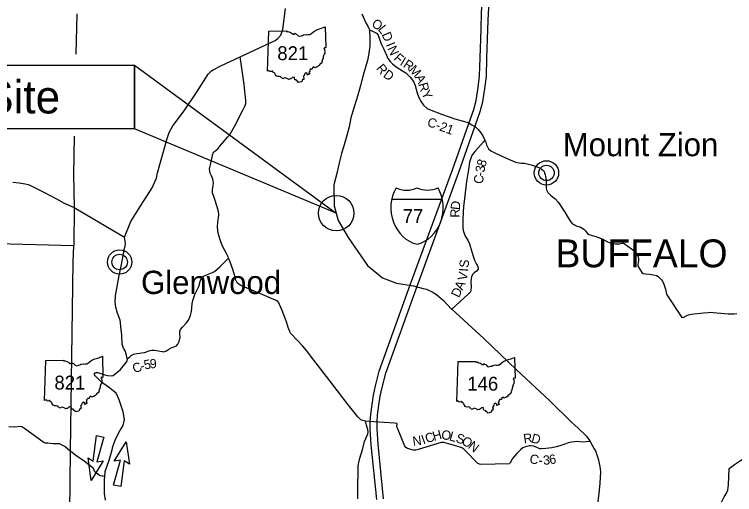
# Model space of a CAD drawing. Extents: x -452339 to 6403467, y -1 to 1814750.
# Drawn here: x -67891 to -44654, y 1625369 to 1640875 of the extents above; entities that cross this region are included whole.
import ezdxf

# ---------------------------------------------------------------- set-up
doc = ezdxf.new("R2010")
doc.units = 0
for name, color, linetype in [('Default', 7, 'Continuous'), ('GM_X_Adjacent_County_Text', 7, 'Continuous'), ('GM_X_County', 7, 'Continuous'), ('GM_X_County_Road', 7, 'Continuous'), ('GM_X_County_Road_Text', 7, 'Continuous'), ('GM_X_Minor_Lake_Text', 7, 'Continuous'), ('GM_X_Section', 7, 'Continuous'), ('GM_X_Section_Text', 7, 'Continuous'), ('GM_X_Township_ROW', 7, 'Continuous')]:
    doc.layers.add(name, color=color, linetype=linetype)

msp = doc.modelspace()

# ---------------------------------------------------------------- linework, layer by layer
at = {"layer": 'Default'}
for p, q in [((-59723, 1639044), (-59681, 1640335)), ((-66916, 1628409), (-66874, 1629700)), ((-53620, 1628373), (-53578, 1629664)), ((-65346, 1626449), (-65238, 1627275)), ((-65238, 1627275), (-65005, 1627228)), ((-65005, 1627228), (-65229, 1626424)), ((-64669, 1626448), (-64288, 1627077)), ((-64288, 1627077), (-64182, 1626349)), ((-65410, 1625829), (-65516, 1626557)), ((-65516, 1626557), (-65346, 1626449)), ((-65030, 1626458), (-65410, 1625829)), ((-65229, 1626424), (-65030, 1626458)), ((-64692, 1625678), (-64469, 1626482)), ((-64469, 1626482), (-64669, 1626448)), ((-64352, 1626458), (-64460, 1625631)), ((-64182, 1626349), (-64352, 1626458)), ((-64460, 1625631), (-64692, 1625678))]:
    msp.add_line(p, q, dxfattribs=at)
for points in [[(-64339, 1633684), (-64133, 1634190), (-63810, 1634709), (-63450, 1635280), (-63304, 1635583), (-63277, 1635756), (-63038, 1636604), (-62979, 1636807), (-62903, 1637066), (-62775, 1637282), (-62415, 1637762), (-62012, 1638356), (-61637, 1638943), (-61528, 1639048), (-61478, 1639088), (-61229, 1639211), (-60612, 1639503), (-59478, 1640037), (-59391, 1640096), (-59300, 1640208), (-59232, 1640383), (-59143, 1641070)], [(-59681, 1640335), (-59109, 1640343), (-59118, 1640328), (-59064, 1640324), (-59007, 1640297), (-58958, 1640280), (-58899, 1640239), (-58863, 1640239), (-58848, 1640273), (-58821, 1640247), (-58789, 1640242), (-58733, 1640180), (-58687, 1640167), (-58631, 1640188), (-58591, 1640191), (-58560, 1640212), (-58482, 1640230), (-58460, 1640219), (-58418, 1640222), (-58397, 1640230), (-58361, 1640223), (-58297, 1640270), (-58232, 1640325), (-58130, 1640377), (-57980, 1640426), (-57860, 1640471), (-57843, 1639801)], [(-56435, 1640374), (-56385, 1640358), (-56246, 1640292), (-56207, 1640264), (-56159, 1640209), (-56099, 1640045), (-56045, 1639904), (-55974, 1639757), (-55890, 1639554), (-55838, 1639454), (-55771, 1639359), (-55692, 1639276), (-55575, 1639185), (-55369, 1639057), (-55261, 1638988), (-55196, 1638929), (-55117, 1638846), (-55044, 1638753), (-55007, 1638683), (-54964, 1638574), (-54899, 1638347), (-54854, 1638219), (-54789, 1638084), (-54689, 1637947), (-54568, 1637840), (-54447, 1637781), (-54113, 1637659), (-53682, 1637499), (-53371, 1637418), (-53291, 1637391), (-53220, 1637358), (-53127, 1637311), (-53011, 1637242), (-52928, 1637161), (-52840, 1637056), (-52777, 1636954), (-52708, 1636813)], [(-57843, 1639801), (-57860, 1639791), (-57888, 1639796), (-57906, 1639777), (-57883, 1639746), (-57873, 1639713), (-57882, 1639676), (-57873, 1639646), (-57879, 1639621), (-57896, 1639595), (-57902, 1639572), (-57917, 1639546), (-57916, 1639532), (-57930, 1639522), (-57927, 1639479), (-57934, 1639456), (-57932, 1639436), (-57955, 1639431), (-57949, 1639414), (-57964, 1639401), (-57961, 1639380), (-57977, 1639365), (-57961, 1639337), (-57974, 1639328), (-57984, 1639294), (-58014, 1639287), (-58071, 1639225), (-58092, 1639201), (-58115, 1639195), (-58128, 1639171), (-58156, 1639171), (-58200, 1639154), (-58227, 1639183), (-58276, 1639148), (-58282, 1639108), (-58343, 1639109), (-58341, 1639089), (-58354, 1639083), (-58367, 1639063), (-58360, 1639026), (-58389, 1639017), (-58385, 1638996), (-58366, 1638983), (-58358, 1638943), (-58389, 1638951), (-58414, 1638917), (-58440, 1638925), (-58432, 1638954), (-58475, 1638989), (-58516, 1638961), (-58538, 1638917), (-58538, 1638887), (-58569, 1638869), (-58549, 1638827), (-58553, 1638798), (-58552, 1638770), (-58591, 1638772), (-58614, 1638697)], [(-60980, 1633002), (-60992, 1633046), (-61051, 1633151), (-61175, 1633395), (-61256, 1633592), (-61312, 1633814), (-61330, 1633906), (-61339, 1634006), (-61324, 1634177), (-61296, 1634393), (-61294, 1634437), (-61321, 1634551), (-61417, 1634861), (-61435, 1634931), (-61468, 1635024), (-61496, 1635100), (-61499, 1635156), (-61497, 1635214), (-61480, 1635355), (-61471, 1635441), (-61475, 1635497), (-61488, 1635555), (-61528, 1635667), (-61571, 1635745), (-61583, 1635806), (-61594, 1635886), (-61563, 1636018), (-61487, 1636371), (-61479, 1636393), (-61457, 1636427), (-61421, 1636461), (-61376, 1636492), (-61326, 1636530), (-61259, 1636615), (-61015, 1636907), (-60956, 1636979), (-60794, 1637252), (-60527, 1637759), (-60442, 1637935), (-60423, 1638001), (-60422, 1638093), (-60477, 1638614), (-60559, 1639209), (-60612, 1639503)], [(-58614, 1638697), (-58681, 1638683), (-58727, 1638675), (-58743, 1638708), (-58776, 1638726), (-58798, 1638760), (-58846, 1638764), (-58857, 1638811), (-58862, 1638849), (-58927, 1638840), (-58945, 1638817), (-58968, 1638810), (-58982, 1638787), (-59013, 1638785), (-59047, 1638774), (-59069, 1638797), (-59125, 1638820), (-59150, 1638832), (-59202, 1638813), (-59213, 1638792), (-59254, 1638801), (-59264, 1638825), (-59289, 1638833), (-59294, 1638858), (-59348, 1638872), (-59389, 1638867), (-59461, 1638887), (-59466, 1638921), (-59490, 1638963), (-59503, 1638991), (-59548, 1639013), (-59558, 1639047), (-59572, 1639046), (-59586, 1639032), (-59637, 1639026), (-59657, 1639040), (-59685, 1639064), (-59723, 1639044)], [(-52708, 1636813), (-52757, 1636763), (-52999, 1636481), (-53019, 1636458)], [(-52708, 1636813), (-52685, 1636749), (-52656, 1636660), (-52629, 1636596), (-52590, 1636530), (-52520, 1636471), (-52391, 1636403), (-52226, 1636326), (-52063, 1636256), (-51823, 1636144), (-51728, 1636103), (-51670, 1636088), (-51544, 1636075), (-51438, 1636068), (-51349, 1636053), (-51215, 1636014), (-51060, 1635968), (-50969, 1635929), (-50915, 1635905), (-50879, 1635881), (-50843, 1635843), (-50802, 1635799), (-50786, 1635747), (-50771, 1635700)], [(-53019, 1636458), (-53020, 1636458), (-53078, 1636390), (-53131, 1636315), (-53169, 1636237), (-53207, 1636105), (-53235, 1635863), (-53299, 1635483), (-53366, 1634931), (-53399, 1634660), (-53414, 1634495), (-53418, 1634227), (-53424, 1633992), (-53410, 1633895), (-53347, 1633717), (-53263, 1633585), (-53209, 1633470), (-53185, 1633396), (-53151, 1633286), (-53088, 1633067), (-53050, 1632944), (-52983, 1632813), (-52948, 1632759), (-52930, 1632697), (-52930, 1632647), (-52983, 1632586), (-53056, 1632535), (-53098, 1632490), (-53146, 1632411), (-53166, 1632255), (-53154, 1632067), (-53159, 1631982), (-53172, 1631914), (-53246, 1631841), (-53777, 1631355)], [(-50771, 1635700), (-50759, 1635647), (-50738, 1635511), (-50729, 1635433), (-50733, 1635331), (-50734, 1635280), (-50719, 1635209), (-50680, 1635123), (-50596, 1635035), (-50541, 1634992), (-50493, 1634962), (-50442, 1634919), (-50344, 1634815), (-50289, 1634736), (-50219, 1634623), (-50135, 1634492), (-50021, 1634304), (-49952, 1634191), (-49905, 1634138), (-49846, 1634087), (-49747, 1634041), (-49637, 1634014), (-49600, 1633997), (-49521, 1633940), (-49468, 1633883), (-49434, 1633840), (-49405, 1633800), (-49360, 1633773), (-49282, 1633742), (-49129, 1633707), (-49075, 1633686), (-48926, 1633629), (-48754, 1633536), (-48650, 1633492), (-48587, 1633485), (-48509, 1633468), (-48363, 1633471), (-48282, 1633488), (-48254, 1633493), (-48213, 1633475), (-48094, 1633389), (-47863, 1633219), (-47832, 1633188), (-47789, 1633104), (-47764, 1633035), (-47751, 1632993), (-47750, 1632937), (-47769, 1632854), (-47776, 1632810), (-47773, 1632768), (-47758, 1632710), (-47643, 1632538), (-47601, 1632511), (-47529, 1632498), (-47392, 1632487), (-47340, 1632478), (-47266, 1632467), (-47178, 1632441), (-47117, 1632414), (-47066, 1632362), (-47015, 1632309), (-46985, 1632266), (-46937, 1632166), (-46886, 1632007), (-46864, 1631893), (-46849, 1631846), (-46800, 1631750), (-46351, 1631086), (-46295, 1631101), (-46192, 1631152), (-46146, 1631173), (-46052, 1631191), (-45659, 1631238), (-45507, 1631253), (-45461, 1631258), (-44859, 1631208), (-44671, 1631206), (-44581, 1631221)], [(-64948, 1625185), (-64981, 1625410), (-64986, 1625696), (-64983, 1625835), (-64973, 1625953), (-64958, 1626117), (-64831, 1626479), (-64734, 1626818), (-64720, 1626926), (-64619, 1627181), (-64488, 1627433), (-64386, 1627601), (-64343, 1627790), (-64382, 1628047), (-64510, 1628425), (-64607, 1628643), (-64858, 1628834), (-65083, 1629003), (-65213, 1629131), (-65284, 1629203), (-65307, 1629235), (-65310, 1629267), (-65288, 1629299), (-65258, 1629311), (-65194, 1629309), (-64975, 1629240), (-64891, 1629211), (-64766, 1629205), (-64706, 1629214), (-64467, 1629410), (-64283, 1629633), (-64255, 1629686), (-64245, 1629734), (-64249, 1629751), (-64273, 1629875), (-64317, 1630013), (-64366, 1630101), (-64410, 1630227), (-64429, 1630518), (-64454, 1630786), (-64465, 1630925), (-64475, 1630999), (-64570, 1631229), (-64615, 1631427), (-64644, 1631581), (-64634, 1631786), (-64507, 1632444), (-64462, 1632697), (-64439, 1632804), (-64345, 1633261), (-64315, 1633406), (-64304, 1633459), (-64321, 1633565), (-64339, 1633684)], [(-64249, 1629751), (-64176, 1629806), (-64122, 1629857), (-64095, 1629879), (-64033, 1629904), (-63941, 1629928), (-63847, 1629935), (-63791, 1629944), (-63693, 1629962), (-63506, 1630020), (-63462, 1630028), (-63384, 1630029), (-63244, 1630012), (-63128, 1629985), (-63086, 1629981), (-63046, 1629986), (-62984, 1630012), (-62906, 1630063), (-62829, 1630108), (-62713, 1630152), (-62663, 1630177), (-62614, 1630225), (-62576, 1630316), (-62547, 1630452), (-62556, 1630560), (-62553, 1630636), (-62529, 1630703), (-62470, 1630773), (-62351, 1630908), (-62271, 1631005), (-62206, 1631152), (-62181, 1631280), (-62155, 1631531), (-62134, 1631637), (-62069, 1631828), (-62018, 1631934), (-61945, 1632085), (-61898, 1632246), (-61881, 1632320), (-61843, 1632376), (-61786, 1632423), (-61666, 1632472), (-61503, 1632541), (-61437, 1632578), (-61262, 1632725), (-60980, 1633002)], [(-55533, 1627513), (-55534, 1627514), (-55544, 1627538), (-55548, 1627564), (-55541, 1627670), (-55625, 1627678), (-56297, 1627719), (-56565, 1627736), (-56649, 1627758), (-56709, 1627785), (-56812, 1627880), (-57151, 1628308), (-57468, 1628718), (-57819, 1629178), (-58234, 1629706), (-58341, 1629851), (-58396, 1629923), (-58468, 1630024), (-58581, 1630161), (-58783, 1630368), (-58940, 1630537), (-58956, 1630559), (-58992, 1630595), (-59004, 1630641), (-59055, 1630768), (-59113, 1630946), (-59255, 1631309), (-59334, 1631507), (-59363, 1631561), (-59395, 1631607), (-59447, 1631642), (-59973, 1631866), (-60582, 1632122), (-60648, 1632159), (-60707, 1632207), (-60749, 1632297), (-60792, 1632469), (-60854, 1632674), (-60939, 1632906), (-60980, 1633002)], [(-66874, 1629700), (-66302, 1629708), (-66311, 1629692), (-66257, 1629689), (-66200, 1629662), (-66151, 1629644), (-66092, 1629603), (-66056, 1629604), (-66041, 1629638), (-66014, 1629611), (-65982, 1629607), (-65926, 1629545), (-65880, 1629532), (-65824, 1629553), (-65783, 1629556), (-65753, 1629577), (-65675, 1629595), (-65652, 1629584), (-65611, 1629587), (-65590, 1629594), (-65554, 1629587), (-65490, 1629634), (-65424, 1629690), (-65323, 1629742), (-65172, 1629791), (-65053, 1629836), (-65035, 1629165)], [(-53578, 1629664), (-53006, 1629672), (-53015, 1629657), (-52961, 1629653), (-52903, 1629626), (-52855, 1629609), (-52796, 1629568), (-52760, 1629568), (-52745, 1629602), (-52718, 1629576), (-52685, 1629571), (-52629, 1629509), (-52583, 1629496), (-52528, 1629517), (-52487, 1629520), (-52457, 1629541), (-52379, 1629559), (-52356, 1629548), (-52315, 1629551), (-52294, 1629559), (-52257, 1629552), (-52194, 1629599), (-52128, 1629654), (-52027, 1629706), (-51876, 1629755), (-51757, 1629800), (-51739, 1629130)], [(-65035, 1629165), (-65053, 1629156), (-65080, 1629160), (-65099, 1629142), (-65076, 1629111), (-65065, 1629077), (-65075, 1629041), (-65065, 1629011), (-65072, 1628986), (-65089, 1628960), (-65095, 1628937), (-65110, 1628911), (-65109, 1628897), (-65122, 1628886), (-65120, 1628844), (-65127, 1628821), (-65124, 1628801), (-65147, 1628796), (-65142, 1628779), (-65157, 1628766), (-65153, 1628744), (-65170, 1628730), (-65154, 1628702), (-65167, 1628693), (-65177, 1628659), (-65207, 1628652), (-65264, 1628590), (-65285, 1628566), (-65308, 1628560), (-65321, 1628536), (-65349, 1628536), (-65392, 1628519), (-65420, 1628548), (-65469, 1628513), (-65474, 1628473), (-65536, 1628474), (-65534, 1628454), (-65547, 1628448), (-65560, 1628427), (-65553, 1628391), (-65581, 1628382), (-65578, 1628361), (-65559, 1628348), (-65551, 1628308), (-65582, 1628316), (-65607, 1628282), (-65633, 1628290), (-65624, 1628319), (-65668, 1628354), (-65709, 1628326), (-65731, 1628281), (-65731, 1628252), (-65762, 1628234), (-65742, 1628192), (-65746, 1628163), (-65745, 1628135), (-65783, 1628136), (-65807, 1628062)], [(-51739, 1629130), (-51757, 1629120), (-51784, 1629125), (-51803, 1629106), (-51780, 1629075), (-51769, 1629041), (-51779, 1629005), (-51769, 1628975), (-51776, 1628950), (-51793, 1628924), (-51799, 1628901), (-51814, 1628875), (-51812, 1628861), (-51826, 1628851), (-51824, 1628808), (-51831, 1628785), (-51828, 1628765), (-51851, 1628760), (-51846, 1628743), (-51860, 1628730), (-51857, 1628709), (-51874, 1628694), (-51858, 1628666), (-51871, 1628657), (-51881, 1628623), (-51910, 1628616), (-51968, 1628554), (-51989, 1628530), (-52012, 1628524), (-52025, 1628500), (-52053, 1628500), (-52096, 1628483), (-52124, 1628512), (-52173, 1628477), (-52178, 1628437), (-52239, 1628438), (-52237, 1628418), (-52251, 1628412), (-52263, 1628392), (-52256, 1628355), (-52285, 1628346), (-52282, 1628325), (-52263, 1628312), (-52255, 1628272), (-52286, 1628280), (-52311, 1628246), (-52337, 1628254), (-52328, 1628283), (-52372, 1628318), (-52413, 1628290), (-52434, 1628246), (-52435, 1628216), (-52466, 1628198), (-52446, 1628156), (-52450, 1628127), (-52449, 1628099), (-52487, 1628101), (-52511, 1628026)], [(-65807, 1628062), (-65874, 1628048), (-65920, 1628040), (-65936, 1628073), (-65969, 1628091), (-65991, 1628125), (-66039, 1628129), (-66050, 1628176), (-66055, 1628214), (-66120, 1628204), (-66138, 1628181), (-66161, 1628175), (-66175, 1628152), (-66206, 1628150), (-66240, 1628139), (-66262, 1628162), (-66317, 1628185), (-66342, 1628196), (-66395, 1628178), (-66405, 1628156), (-66447, 1628166), (-66456, 1628190), (-66481, 1628198), (-66487, 1628223), (-66541, 1628237), (-66582, 1628232), (-66654, 1628252), (-66659, 1628286), (-66683, 1628327), (-66695, 1628356), (-66741, 1628378), (-66751, 1628412), (-66765, 1628411), (-66779, 1628397), (-66830, 1628390), (-66850, 1628404), (-66878, 1628428), (-66916, 1628409)], [(-52511, 1628026), (-52577, 1628012), (-52624, 1628004), (-52640, 1628037), (-52673, 1628055), (-52695, 1628089), (-52742, 1628093), (-52754, 1628140), (-52759, 1628178), (-52824, 1628169), (-52842, 1628146), (-52865, 1628139), (-52878, 1628116), (-52910, 1628114), (-52944, 1628103), (-52966, 1628126), (-53021, 1628149), (-53046, 1628161), (-53098, 1628142), (-53109, 1628121), (-53150, 1628130), (-53160, 1628154), (-53185, 1628162), (-53191, 1628187), (-53244, 1628201), (-53286, 1628196), (-53358, 1628216), (-53362, 1628250), (-53387, 1628292), (-53399, 1628320), (-53445, 1628342), (-53455, 1628376), (-53469, 1628375), (-53482, 1628361), (-53533, 1628355), (-53553, 1628369), (-53582, 1628393), (-53620, 1628373)], [(-68067, 1627567), (-67879, 1627558), (-67697, 1627574), (-67649, 1627567), (-67568, 1627518), (-66932, 1627056), (-66898, 1627036), (-66816, 1627036), (-66643, 1627015), (-66444, 1627016), (-66250, 1626923), (-66076, 1626771)], [(-56805, 1625229), (-56810, 1625638), (-56804, 1626108), (-56797, 1626293), (-56780, 1626401), (-56745, 1626547), (-56653, 1626858), (-56591, 1627081), (-56549, 1627178), (-56488, 1627334), (-56479, 1627384), (-56489, 1627456), (-56534, 1627612), (-56565, 1627736)], [(-49319, 1627087), (-49442, 1627071), (-49570, 1627064), (-49642, 1627070), (-49748, 1627081), (-49824, 1627078), (-49915, 1627065), (-50019, 1627039), (-50131, 1626996), (-50290, 1626940), (-50410, 1626915), (-50556, 1626878), (-50744, 1626855), (-50892, 1626844), (-50942, 1626851), (-51056, 1626900), (-51144, 1626928), (-51220, 1626941), (-51284, 1626939), (-51358, 1626926), (-51434, 1626903), (-51483, 1626877), (-51559, 1626820), (-51682, 1626695), (-51827, 1626520), (-51868, 1626451), (-51896, 1626401), (-51912, 1626363), (-52837, 1626342), (-52887, 1626347), (-52937, 1626369), (-53344, 1626794), (-53390, 1626840), (-53432, 1626866), (-53507, 1626901), (-54032, 1627047), (-54086, 1627055), (-54117, 1627051), (-54860, 1626824), (-54943, 1626808), (-55015, 1626809), (-55210, 1626862), (-55236, 1626878), (-55260, 1626891), (-55292, 1626935), (-55533, 1627513)], [(-64973, 1625953), (-65028, 1625963), (-65061, 1625966), (-65113, 1625972), (-65147, 1625988), (-65294, 1626107), (-65334, 1626207), (-65639, 1626452), (-65912, 1626634), (-66076, 1626771)], [(-44955, 1622772), (-44956, 1622773), (-44951, 1622812), (-44961, 1622892), (-45003, 1623040), (-45017, 1623148), (-45009, 1623362), (-44991, 1623560), (-44986, 1623652), (-44982, 1624125), (-44988, 1624557), (-44996, 1624632), (-45048, 1624874), (-45073, 1625030), (-45073, 1625094), (-45059, 1625168), (-44987, 1625298), (-44923, 1625398), (-44877, 1625509), (-44847, 1625681), (-44827, 1626210)]]:
    msp.add_lwpolyline(points, dxfattribs=at)
for centre, major_axis, start_param, end_param in [((-54655, 1634631), (0, -1211), 4.15077, 6.05619), ((-55238, 1636166), (0, -966), 5.88324, 6.683049), ((-55145, 1634631), (0, -1211), 0.227007, 2.13242), ((-54561, 1636167), (0, -966), 5.883359, 6.683012)]:
    msp.add_ellipse(centre, major_axis=major_axis, ratio=0.9, start_param=start_param, end_param=end_param, dxfattribs=at)
at = {"layer": 'GM_X_County_Road'}
for points in [[(-55118, 1632146), (-53761, 1635853), (-53231, 1637347), (-53165, 1637534), (-53072, 1637801), (-52997, 1638100), (-52927, 1638510), (-52882, 1638890), (-52866, 1639472), (-52834, 1640397), (-52818, 1640935), (-52772, 1641492), (-52741, 1641959), (-52678, 1642361), (-52534, 1643071), (-52423, 1643592)], [(-54911, 1632070), (-53554, 1635778), (-53023, 1637274), (-52957, 1637462), (-52861, 1637738), (-52782, 1638054), (-52709, 1638479), (-52662, 1638874), (-52647, 1639465), (-52614, 1640390), (-52599, 1640922), (-52553, 1641476), (-52522, 1641934), (-52461, 1642323), (-52319, 1643026), (-52208, 1643546)], [(-56677, 1640893), (-56592, 1640699), (-56547, 1640607), (-56480, 1640473), (-56451, 1640422), (-56435, 1640374), (-56422, 1640086), (-56420, 1639852), (-56450, 1639636), (-56450, 1639635)], [(-56450, 1639635), (-56453, 1639610), (-56499, 1639383), (-56639, 1638909), (-56725, 1638583), (-56811, 1638272), (-56921, 1637928), (-57004, 1637646), (-57037, 1637536), (-57095, 1637245), (-57168, 1636964), (-57252, 1636666), (-57337, 1636387), (-57415, 1636086), (-57474, 1635783), (-57587, 1635369), (-57569, 1634689), (-57445, 1634224), (-57127, 1633667), (-56502, 1632771), (-56011, 1632364), (-55568, 1632193), (-55014, 1632108), (-54705, 1632027), (-54592, 1632004), (-54416, 1631914), (-54271, 1631831), (-54048, 1631635), (-53785, 1631362), (-53777, 1631355), (-52749, 1630405), (-51696, 1629398), (-50628, 1628408), (-50622, 1628403), (-49894, 1627686), (-49715, 1627528), (-49435, 1627251), (-49319, 1627087), (-49182, 1626851), (-49146, 1626787), (-49056, 1626522), (-49007, 1626279), (-48977, 1626101), (-49005, 1625736), (-49038, 1625401), (-49087, 1624992)], [(-67945, 1635453), (-67740, 1635432), (-67540, 1635407), (-67451, 1635386), (-67371, 1635348), (-67198, 1635259), (-66968, 1635144), (-66763, 1635038), (-66532, 1634915), (-66283, 1634780), (-65962, 1634643)], [(-65962, 1634643), (-64339, 1633684)], [(-56201, 1625210), (-56378, 1626980), (-56410, 1627487), (-56407, 1627724), (-56390, 1627957), (-56350, 1628282), (-56307, 1628583), (-56243, 1628884), (-56120, 1629355), (-55118, 1632145)], [(-55982, 1625230), (-56159, 1626997), (-56190, 1627493), (-56187, 1627715), (-56171, 1627936), (-56132, 1628253), (-56091, 1628544), (-56029, 1628833), (-55910, 1629290), (-54911, 1632071)]]:
    msp.add_lwpolyline(points, dxfattribs=at)
at = {"layer": 'GM_X_County_Road_Text'}
for centre, radius in [((-50724, 1635757), 393), ((-50724, 1635757), 249), ((-64496, 1632880), 393), ((-64496, 1632880), 249)]:
    msp.add_circle(centre, radius, dxfattribs=at)
at = {"layer": 'GM_X_Minor_Lake_Text'}
msp.add_line((-55714, 1634904), (-54083, 1634904), dxfattribs=at)
at = {"layer": 'GM_X_Section'}
msp.add_lwpolyline([(-44827, 1626210), (-44657, 1626340), (-44564, 1626407), (-44461, 1626475), (-44366, 1626535), (-44325, 1626576), (-44284, 1626651), (-44246, 1626848), (-44218, 1627114), (-44192, 1627431), (-44160, 1627582), (-44072, 1627788), (-43910, 1628025), (-43866, 1628060), (-43819, 1628087), (-43642, 1628124), (-43558, 1628149), (-43520, 1628151)], dxfattribs=at)
at = {"layer": 'GM_X_Section_Text'}
for p, q in [((-65878, 1640897), (-65905, 1639596)), ((-65960, 1636947), (-65986, 1635702)), ((-65986, 1635702), (-65962, 1634643)), ((-65962, 1634643), (-65969, 1633411)), ((-71296, 1633554), (-65969, 1633411)), ((-65994, 1632878), (-65969, 1633411)), ((-65994, 1632878), (-65969, 1633411)), ((-65994, 1632878), (-65969, 1633411)), ((-66076, 1626771), (-65994, 1632878)), ((-66076, 1626771), (-65994, 1632878)), ((-66122, 1623362), (-66076, 1626771))]:
    msp.add_line(p, q, dxfattribs=at)
at = {"layer": 'GM_X_Township_ROW'}
for p, q in [((-74256, 1639239), (-64016, 1639239)), ((-64016, 1637179), (-74256, 1637179))]:
    msp.add_line(p, q, dxfattribs=at)
msp.add_lwpolyline([(-64016, 1639239), (-64016, 1637179)], dxfattribs=at)
msp.add_lwpolyline([(-64016, 1639239), (-57507, 1634457), (-64016, 1637179)], close=True, dxfattribs=at)
msp.add_circle((-57507, 1634457), 572, dxfattribs=at)

# ---------------------------------------------------------------- texts
at = {"layer": 'Default'}
for s, p in [('821', (-59408, 1639398)), ('77', (-55363, 1634140)), ('821', (-66601, 1628762)), ('146', (-53280, 1628727))]:
    msp.add_text(s, height=447.7, dxfattribs=at).set_placement(p)
at = {"layer": 'GM_X_Adjacent_County_Text'}
for s, height, p in [('Mount Zion', 750, (-50197, 1636296)), ('BUFFALO', 900, (-50432, 1632709)), ('Glenwood', 750, (-63804, 1631847))]:
    msp.add_text(s, height=height, rotation=0, dxfattribs=at).set_placement(p)
at = {"layer": 'GM_X_County'}
for s, rotation, p in [('O', 333.2183, (-56387, 1640485)), ('L', 308.7421, (-56178, 1640388)), ('D', 293.013, (-56048, 1640231)), ('I', 292.2949, (-55910, 1639903)), ('N', 294.0168, (-55860, 1639780)), ('F', 317.8384, (-55673, 1639430)), ('I', 328.6139, (-55474, 1639257)), ('R', 325.7882, (-55372, 1639195)), ('R', 308.5227, (-56234, 1639129)), ('M', 312.863, (-55182, 1639068)), ('D', 324.605, (-56015, 1638874)), ('A', 296.6433, (-54973, 1638848)), ('R', 286.0151, (-54860, 1638626)), ('Y', 295.5868, (-54772, 1638338)), ('C-21', 339.725, (-54597, 1637282)), ('8', 72.1493, (-52703, 1635930)), ('3', 82.7498, (-52723, 1635761)), ('C', 80.5787, (-52785, 1635384)), ('-', 80.9845, (-52744, 1635629)), ('D', 83.7366, (-53523, 1634550)), ('R', 88.9774, (-53527, 1634311)), ('S', 85.4814, (-53238, 1632684)), ('V', 79.2362, (-53301, 1632264)), ('I', 86.0564, (-53246, 1632562)), ('A', 65.3128, (-53435, 1631948)), ('D', 64.9811, (-53547, 1631707)), ('5', 11.5896, (-63681, 1629404)), ('9', 5.2261, (-63509, 1629440)), ('C', 21.1349, (-64016, 1629281)), ('-', 17.9532, (-63790, 1629368)), ('C', 17.0944, (-54587, 1627027)), ('H', 15.7673, (-54353, 1627099)), ('O', 350.1304, (-54134, 1627169)), ('L', 344.5261, (-53882, 1627126)), ('S', 343.821, (-53667, 1627066)), ('R', 8.3189, (-51447, 1627021)), ('D', 346.0159, (-51233, 1627058)), ('N', 7.6397, (-55024, 1626939)), ('I', 18.5685, (-54702, 1626989)), ('O', 329.9384, (-53490, 1627017)), ('N', 321.8215, (-53271, 1626891)), ('C', 345.1591, (-51295, 1626404)), ('3', 5.0048, (-50821, 1626327)), ('6', 9.4377, (-50612, 1626346)), ('-', 358.2349, (-50983, 1626330))]:
    msp.add_text(s, height=300, rotation=rotation, dxfattribs=at).set_placement(p)
at = {"layer": 'GM_X_Township_ROW'}
msp.add_text('Project Site', height=1063.82, dxfattribs=at).set_placement((-73689, 1637677))

doc.saveas('drawing.dxf')
